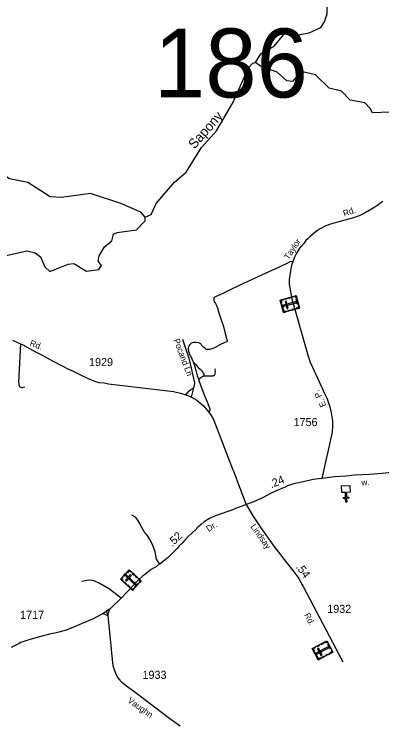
# Model space of a CAD drawing. Extents: x 2220236 to 2384410, y 720751 to 894131.
# Drawn here: x 2299448 to 2305133, y 776939 to 787885 of the extents above; entities that cross this region are included whole.
import ezdxf

# ---------------------------------------------------------------- set-up
doc = ezdxf.new("R2010")
doc.units = 0
for name, color, linetype in [('Exist Cultural Cemetery CELL', 7, 'Continuous'), ('Exist Cultural Church CELL', 7, 'Continuous'), ('Exist Hydrographic Creek Single Shore', 7, 'Continuous'), ('Exist Hydrographic Creek Single Shore Label', 7, 'Continuous'), ('Exist Hydrographic Misc Water Feature', 7, 'Continuous'), ('Exist Road Non-System Type 51', 7, 'Continuous'), ('Exist Road Non-System Type 51 Label', 7, 'Continuous'), ('Exist Road Secondary Mileage Hundredths English Label', 7, 'Continuous'), ('Exist Road Secondary Structure Standard Bridge Number Label', 7, 'Continuous'), ('Exist Road Secondary Type 20 Attributed', 7, 'Continuous'), ('Exist Road Secondary Type 51 Attributed', 7, 'Continuous'), ('Exist Road Secondary Type 51 Label', 7, 'Continuous'), ('Exist Road Secondary Type 51 Number Label', 7, 'Continuous')]:
    doc.layers.add(name, color=color, linetype=linetype)

msp = doc.modelspace()

# ---------------------------------------------------------------- linework, layer by layer
at = {"layer": 'Exist Cultural Cemetery CELL'}
for points in [[(2303613, 783271), (2303560, 783463), (2303806, 783531), (2303859, 783339)], [(2303814, 783499), (2303803, 783496), (2303797, 783517), (2303759, 783506), (2303756, 783517), (2303806, 783531)], [(2303602, 783474), (2303605, 783463), (2303574, 783455), (2303585, 783416), (2303574, 783413), (2303560, 783463)], [(2303613, 783384), (2303618, 783366), (2303813, 783420), (2303808, 783438)], [(2303675, 783483), (2303634, 783471), (2303631, 783482), (2303672, 783494)], [(2303668, 783328), (2303686, 783333), (2303655, 783447), (2303637, 783442)], [(2303739, 783501), (2303697, 783489), (2303694, 783500), (2303736, 783512)], [(2303832, 783391), (2303810, 783473), (2303821, 783476), (2303843, 783394)], [(2303594, 783342), (2303580, 783392), (2303591, 783395), (2303605, 783345)], [(2303655, 783282), (2303652, 783293), (2303621, 783285), (2303610, 783324), (2303600, 783321), (2303613, 783271)], [(2303727, 783302), (2303685, 783291), (2303682, 783302), (2303724, 783313)], [(2303791, 783320), (2303750, 783309), (2303747, 783320), (2303788, 783331)], [(2303850, 783371), (2303839, 783368), (2303845, 783347), (2303806, 783336), (2303809, 783325), (2303859, 783339)], [(2301092, 779146), (2301227, 779292), (2301414, 779118), (2301278, 778973)], [(2301259, 779262), (2301251, 779254), (2301228, 779276), (2301200, 779246), (2301192, 779254), (2301227, 779292)], [(2301123, 779116), (2301131, 779125), (2301107, 779146), (2301135, 779176), (2301127, 779184), (2301092, 779146)], [(2301142, 779200), (2301177, 779238), (2301186, 779230), (2301150, 779192)], [(2301169, 779129), (2301183, 779117), (2301263, 779203), (2301249, 779216)], [(2301187, 779206), (2301174, 779192), (2301323, 779054), (2301336, 779068)], [(2301305, 779204), (2301273, 779234), (2301281, 779242), (2301312, 779212)], [(2301353, 779159), (2301321, 779189), (2301329, 779197), (2301361, 779168)], [(2301391, 779094), (2301383, 779102), (2301398, 779118), (2301368, 779146), (2301376, 779154), (2301414, 779118)], [(2301178, 779066), (2301146, 779095), (2301154, 779104), (2301185, 779074)], [(2301227, 779020), (2301195, 779050), (2301203, 779058), (2301235, 779028)], [(2301309, 779022), (2301367, 779085), (2301375, 779077), (2301317, 779015)], [(2301301, 778997), (2301292, 779005), (2301277, 778988), (2301248, 779016), (2301240, 779008), (2301278, 778973)], [(2304150, 777897), (2304057, 778073), (2304283, 778192), (2304375, 778016)], [(2304224, 778148), (2304186, 778128), (2304180, 778138), (2304219, 778158)], [(2304298, 778162), (2304288, 778157), (2304278, 778176), (2304242, 778158), (2304237, 778168), (2304283, 778192)], [(2304096, 778093), (2304101, 778083), (2304073, 778068), (2304091, 778032), (2304082, 778027), (2304057, 778073)], [(2304166, 778117), (2304127, 778097), (2304122, 778107), (2304160, 778127)], [(2304125, 778007), (2304134, 777991), (2304313, 778085), (2304305, 778101)], [(2304191, 777965), (2304208, 777973), (2304153, 778078), (2304137, 778069)], [(2304339, 778061), (2304299, 778136), (2304309, 778141), (2304349, 778066)], [(2304360, 778045), (2304350, 778039), (2304360, 778020), (2304324, 778001), (2304330, 777991), (2304375, 778015)], [(2304116, 777962), (2304092, 778008), (2304102, 778014), (2304126, 777968)], [(2304188, 777917), (2304183, 777927), (2304155, 777912), (2304136, 777948), (2304126, 777943), (2304150, 777897)], [(2304254, 777952), (2304216, 777931), (2304210, 777942), (2304249, 777962)], [(2304314, 777983), (2304275, 777963), (2304270, 777973), (2304308, 777993)]]:
    msp.add_lwpolyline(points, close=True, dxfattribs=at)
at = {"layer": 'Exist Cultural Church CELL'}
msp.add_lwpolyline([(2304642, 780491), (2304585, 780488), (2304589, 780412), (2304621, 780414), (2304621, 780398), (2304589, 780396), (2304592, 780336), (2304576, 780335), (2304573, 780395), (2304542, 780394), (2304541, 780410), (2304573, 780411), (2304569, 780487), (2304512, 780485), (2304507, 780591), (2304637, 780597)], close=True, dxfattribs=at)
at = {"layer": 'Exist Hydrographic Creek Single Shore'}
for points in [[(2303180, 787137), (2303262, 787271), (2303469, 787391), (2303617, 787568), (2303699, 787617), (2303808, 787560), (2304008, 787597), (2304190, 787680), (2304248, 787765), (2304288, 787891), (2304284, 788239), (2304259, 788280), (2304265, 788415), (2304479, 788660), (2304704, 788719), (2304776, 788961), (2304783, 789102), (2304972, 789324), (2305096, 789424), (2305262, 789440)], [(2301473, 784744), (2301564, 784787), (2301646, 784954), (2301925, 785284), (2302107, 785442), (2302344, 785820), (2302575, 786082), (2302836, 786525), (2303072, 787054), (2303138, 787129), (2303180, 787137)], [(2301473, 784744), (2301406, 784820), (2301096, 784958), (2300628, 785109), (2300179, 785048), (2300004, 785061), (2299660, 785283), (2299376, 785337), (2299074, 785528), (2298880, 785708), (2298713, 785789), (2297953, 785949), (2297647, 785870), (2297517, 785867), (2297390, 785912), (2297170, 785999), (2297067, 786022), (2296687, 786025), (2296537, 786009), (2296397, 785849), (2296314, 785813), (2296248, 785813)], [(2299305, 784146), (2299646, 784226), (2299771, 784195), (2299855, 784130), (2299924, 783978), (2299999, 783906), (2300281, 784016), (2300373, 784026), (2300566, 783909), (2300757, 783937), (2300798, 783997), (2300747, 784064), (2300763, 784147), (2300845, 784288), (2300960, 784381), (2300984, 784481), (2301042, 784506), (2301342, 784551), (2301473, 784688), (2301473, 784744)]]:
    msp.add_lwpolyline(points, dxfattribs=at)
at = {"layer": 'Exist Hydrographic Misc Water Feature'}
msp.add_lwpolyline([(2306850, 785068), (2306624, 785184), (2306373, 785265), (2306247, 785346), (2305923, 786058), (2305839, 786133), (2305672, 786198), (2305430, 786238), (2305254, 786368), (2304987, 786357), (2304953, 786425), (2304869, 786513), (2304644, 786553), (2304509, 786692), (2304317, 786740), (2304106, 786948), (2303931, 786987), (2303840, 786944), (2303749, 786845), (2303666, 786851), (2303514, 786990), (2303255, 787081), (2303180, 787137)], dxfattribs=at)
at = {"layer": 'Exist Road Non-System Type 51'}
for p, q in [((2302189, 781961), (2302228, 782105)), ((2300822, 778613), (2300894, 778584))]:
    msp.add_line(p, q, dxfattribs=at)
for points in [[(2303756, 784054), (2303723, 784058), (2303708, 784053), (2303674, 784035), (2303545, 783972), (2303330, 783874), (2303139, 783784), (2302917, 783682), (2302787, 783619), (2302674, 783565), (2302592, 783530), (2302561, 783514), (2302547, 783507), (2302538, 783500), (2302533, 783488), (2302533, 783473), (2302533, 783457), (2302538, 783444), (2302548, 783428), (2302561, 783408), (2302577, 783380), (2302590, 783340), (2302614, 783264), (2302650, 783159), (2302683, 783053), (2302711, 782944), (2302731, 782870), (2302742, 782837), (2302741, 782828), (2302736, 782819), (2302723, 782809), (2302697, 782799), (2302638, 782774), (2302554, 782728), (2302507, 782709), (2302483, 782703), (2302466, 782699), (2302442, 782697), (2302428, 782698), (2302413, 782702), (2302400, 782713), (2302382, 782728), (2302366, 782746), (2302347, 782765), (2302332, 782786), (2302301, 782799), (2302264, 782807), (2302235, 782806), (2302203, 782803), (2302185, 782794), (2302169, 782779), (2302153, 782759), (2302144, 782740), (2302139, 782721), (2302138, 782698), (2302141, 782674), (2302160, 782628), (2302183, 782579), (2302203, 782528), (2302216, 782506)], [(2299548, 782788), (2299516, 782194), (2299521, 782170), (2299521, 782150), (2299525, 782136), (2299531, 782128), (2299563, 782109), (2299575, 782109), (2299591, 782113), (2299611, 782121)], [(2302228, 782105), (2302232, 782119), (2302239, 782173), (2302239, 782183), (2302166, 782521), (2302149, 782574), (2302056, 782851)], [(2302216, 782506), (2302256, 782467), (2302290, 782427), (2302323, 782393), (2302342, 782374), (2302358, 782354), (2302371, 782332), (2302381, 782316), (2302382, 782310), (2302383, 782299), (2302382, 782289)], [(2302216, 782506), (2302235, 782453), (2302255, 782374), (2302279, 782292), (2302296, 782243), (2302310, 782201)], [(2302382, 782289), (2302405, 782292), (2302436, 782293), (2302486, 782291), (2302507, 782289), (2302518, 782289), (2302525, 782292), (2302537, 782298), (2302544, 782303), (2302549, 782311), (2302554, 782322), (2302557, 782336), (2302561, 782359), (2302558, 782380), (2302561, 782399)], [(2302310, 782201), (2302309, 782228), (2302313, 782243), (2302319, 782252), (2302332, 782265), (2302348, 782277), (2302366, 782284), (2302382, 782289)], [(2302102, 781996), (2302149, 782051), (2302178, 782079), (2302228, 782105)], [(2302310, 782201), (2302332, 782136), (2302387, 781999), (2302432, 781886), (2302457, 781823), (2302468, 781794), (2302473, 781781), (2302473, 781767), (2302471, 781758), (2302462, 781743), (2302455, 781734)], [(2301702, 779377), (2301663, 779430), (2301651, 779454), (2301626, 779566), (2301597, 779658), (2301568, 779725), (2301542, 779769), (2301505, 779825), (2301479, 779852), (2301465, 779872), (2301403, 779981), (2301391, 780007), (2301358, 780059), (2301324, 780103), (2301310, 780112), (2301280, 780128), (2301268, 780136)], [(2301103, 778853), (2301037, 778904), (2300924, 778993), (2300760, 779086), (2300696, 779116), (2300660, 779127), (2300618, 779129), (2300573, 779127), (2300493, 779110)], [(2300894, 778584), (2300918, 778657), (2300931, 778687)]]:
    msp.add_lwpolyline(points, dxfattribs=at)
at = {"layer": 'Exist Road Secondary Type 20 Attributed'}
msp.add_lwpolyline([(2303034, 780298), (2303140, 780125), (2303254, 779957), (2303465, 779657), (2303657, 779406), (2303757, 779281), (2303852, 779156), (2303900, 779059), (2303918, 779031), (2304531, 777868)], dxfattribs=at)
at = {"layer": 'Exist Road Secondary Type 51 Attributed'}
for points in [[(2305147, 784988), (2305103, 784956), (2305073, 784932), (2305023, 784897), (2304972, 784867), (2304876, 784813), (2304781, 784768), (2304696, 784736), (2304483, 784677), (2304341, 784639), (2304267, 784609), (2304191, 784569), (2304123, 784527), (2304064, 784480), (2304024, 784445), (2303989, 784410), (2303960, 784382), (2303925, 784338), (2303897, 784308), (2303862, 784264), (2303805, 784169), (2303784, 784125), (2303771, 784095), (2303756, 784054), (2303743, 784017), (2303726, 783947), (2303713, 783873), (2303699, 783784), (2303700, 783706), (2303739, 783481), (2303992, 782594), (2304025, 782504), (2304205, 782109), (2304247, 782015), (2304285, 781935), (2304308, 781873), (2304326, 781826), (2304345, 781750), (2304371, 781594), (2304371, 781521), (2304364, 781418), (2304204, 780704)], [(2299422, 782841), (2299548, 782788), (2299597, 782764), (2299631, 782743), (2299685, 782713), (2299770, 782667), (2299869, 782615), (2300039, 782524), (2300188, 782444), (2300286, 782393), (2300358, 782362), (2300403, 782340), (2300527, 782279), (2300590, 782248), (2300690, 782208), (2300756, 782187), (2300839, 782181), (2300909, 782168), (2301911, 782048), (2302022, 782022), (2302102, 781996), (2302131, 781988), (2302189, 781961), (2302271, 781913), (2302373, 781829), (2302455, 781734), (2302495, 781676), (2302529, 781613), (2302827, 780838), (2302842, 780807), (2302934, 780568), (2302946, 780534), (2302963, 780486), (2302987, 780421), (2303034, 780298)], [(2306813, 781168), (2306756, 781140), (2306688, 781106), (2306620, 781081), (2306545, 781053), (2306477, 781026), (2306404, 781001), (2306295, 780972), (2306118, 780931), (2305839, 780875), (2305624, 780839), (2305368, 780807), (2305136, 780782), (2304937, 780766), (2304710, 780753), (2304576, 780737), (2304406, 780728), (2304204, 780704)], [(2304204, 780704), (2304161, 780700), (2304113, 780691), (2304072, 780685), (2304007, 780671), (2303939, 780657), (2303852, 780637), (2303789, 780626), (2303737, 780610), (2303676, 780589), (2303638, 780571), (2303536, 780529), (2303424, 780476), (2303296, 780408), (2303137, 780337), (2303034, 780298)], [(2303034, 780298), (2302971, 780276), (2302895, 780248), (2302858, 780232), (2302812, 780215), (2302736, 780185), (2302577, 780133), (2302499, 780101), (2302468, 780083), (2302440, 780067), (2302411, 780046), (2302388, 780032), (2302341, 779993), (2302290, 779950), (2302245, 779904), (2302200, 779860), (2302142, 779809), (2302089, 779751), (2302051, 779708), (2302001, 779659), (2301966, 779620), (2301935, 779587), (2301904, 779556), (2301876, 779528), (2301832, 779486), (2301702, 779377), (2301665, 779356), (2301647, 779343), (2301613, 779319), (2301568, 779293), (2301521, 779261), (2301478, 779225), (2301433, 779190), (2301364, 779130), (2301103, 778853), (2301078, 778827), (2301060, 778813), (2300995, 778748), (2300931, 778687), (2300902, 778671), (2300875, 778652)], [(2300875, 778652), (2300854, 778635), (2300822, 778613), (2300736, 778567), (2300668, 778534), (2300563, 778486), (2300366, 778403), (2300252, 778359), (2300141, 778328), (2300075, 778313), (2300014, 778301), (2299959, 778283), (2299896, 778269), (2299745, 778229), (2299642, 778198), (2299552, 778165), (2299524, 778153), (2299462, 778120), (2299400, 778089)], [(2300875, 778652), (2300894, 778584), (2300946, 778065), (2300951, 778003), (2300975, 777808), (2300977, 777796), (2301022, 777674), (2301049, 777619), (2301084, 777584), (2301113, 777555), (2301206, 777482), (2301244, 777456), (2301299, 777411), (2301379, 777353), (2301856, 776991), (2302013, 776879)]]:
    msp.add_lwpolyline(points, dxfattribs=at)

# ---------------------------------------------------------------- texts
at = {"layer": 'Exist Hydrographic Creek Single Shore Label'}
msp.add_text('Sapony', height=150, rotation=48.5924, dxfattribs=at).set_placement((2302236, 785790))
at = {"layer": 'Exist Road Non-System Type 51 Label'}
msp.add_text('Pocand Ln', height=95, rotation=290.8424, dxfattribs=at).set_placement((2301909, 782845))
at = {"layer": 'Exist Road Secondary Mileage Hundredths English Label'}
for s, rotation, p in [('.24', 22.5927, (2303424, 780550)), ('.52', 44.3109, (2301892, 779640)), ('.54', 307.3489, (2303796, 779332))]:
    msp.add_text(s, height=125, rotation=rotation, dxfattribs=at).set_placement(p)
at = {"layer": 'Exist Road Secondary Structure Standard Bridge Number Label'}
msp.add_text('186', height=1066.3, dxfattribs=at).set_placement((2301610, 786596))
at = {"layer": 'Exist Road Secondary Type 51 Label'}
for s, rotation, p in [('Rd.', 19.3542, (2304553, 784752)), ('Taylor', 55.9363, (2303690, 784079)), ('Rd.', 339.2946, (2299681, 782760)), ('E. P.', 115.0526, (2304275, 781833)), ('w.', 3.7723, (2304820, 780593)), ('Dr.', 33.0662, (2302456, 779874)), ('Lindsay', 305.4655, (2303097, 779958)), ('Rd.', 297.7622, (2303929, 778593)), ('Vaughn', 324.3635, (2301195, 777250))]:
    msp.add_text(s, height=95, rotation=rotation, dxfattribs=at).set_placement(p)
at = {"layer": 'Exist Road Secondary Type 51 Number Label'}
for s, p in [('1929', (2300605, 782441)), ('1756', (2303767, 781513)), ('1932', (2304288, 778624)), ('1717', (2299540, 778532)), ('1933', (2301432, 777604))]:
    msp.add_text(s, height=125, dxfattribs=at).set_placement(p)

doc.saveas('drawing.dxf')
